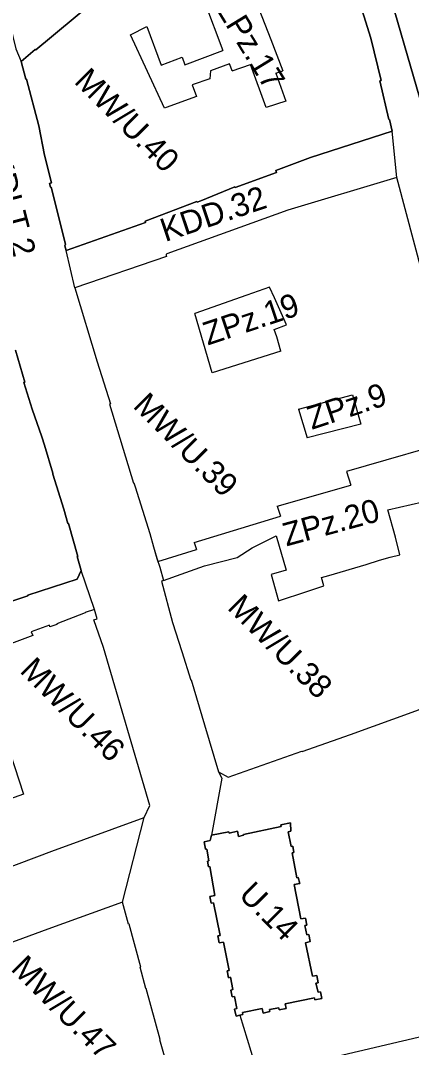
# Model space of a CAD drawing. Extents: x 7423835 to 7425280, y 5546086 to 5547600.
# Drawn here: x 7424273.1 to 7424373.9, y 5546340.4 to 5546605 of the extents above; entities that cross this region are included whole.
import ezdxf

# ---------------------------------------------------------------- set-up
doc = ezdxf.new("R2010")
doc.units = 0
for name, color, linetype in [('linie rozgraniczające', 7, 'Continuous'), ('obowiazujace linie zabudowy', 7, 'Continuous'), ('przeznaczenia terenów', 7, 'Continuous')]:
    doc.layers.add(name, color=color, linetype=linetype)

msp = doc.modelspace()

# ---------------------------------------------------------------- linework, layer by layer
at = {"layer": 'linie rozgraniczające'}
for p, q in [((7424320.53, 5546609.85), (7424325.27, 5546597.26)), ((7424327.69, 5546592.07), (7424332.39, 5546593.73)), ((7424370.16, 5546564.59), (7424368.92, 5546576.52)), ((7424287.1, 5546536.15), (7424284.89, 5546545.76)), ((7424340.24, 5546519.82), (7424322.49, 5546514.25)), ((7424344.77, 5546504.87), (7424346.97, 5546497.47)), ((7424339.31, 5546479.88), (7424358.24, 5546485.3)), ((7424339.31, 5546479.88), (7424340.11, 5546477.35)), ((7424292.16, 5546453.27), (7424288.73, 5546463.32)), ((7424299.42, 5546377.82), (7424304.94, 5546399.71)), ((7424300.93, 5546372.18), (7424299.42, 5546377.82))]:
    msp.add_line(p, q, dxfattribs=at)
for points in [[(7424415.44, 5546675.99), (7424420.93, 5546660.04), (7424421.75, 5546657.53), (7424423.79, 5546651.25), (7424427.88, 5546638.9), (7424441.46, 5546599.12), (7424429.54, 5546594.89), (7424419.97, 5546592.1), (7424408.6, 5546588.75), (7424395.96, 5546584.68), (7424377.65, 5546579.36), (7424357.5, 5546649.05), (7424367.44, 5546652.38), (7424372.88, 5546654.73), (7424377.74, 5546656.83), (7424384.62, 5546660.5)], [(7424264.54, 5546627.07), (7424265.35, 5546624.27), (7424271.84, 5546597.69), (7424273.24, 5546594.48)], [(7424357.59, 5546619.22), (7424363.45, 5546600.46), (7424366.11, 5546589.55), (7424365.71, 5546589.45), (7424368.07, 5546579.5), (7424368.22, 5546579.54), (7424368.92, 5546576.52), (7424347.88, 5546569.7), (7424338.93, 5546566.38), (7424339.13, 5546565.91), (7424328.45, 5546561.99), (7424328.37, 5546562.15), (7424323.98, 5546560.37), (7424319.59, 5546558.59), (7424318.62, 5546558.21), (7424318.55, 5546558.42), (7424305.2, 5546553.33), (7424305.32, 5546552.95), (7424284.89, 5546545.76)], [(7424273.24, 5546594.48), (7424276.9, 5546597.55), (7424277.06, 5546597.51), (7424281.07, 5546600.81), (7424295.83, 5546613.18)], [(7424332.31, 5546613.36), (7424332.85, 5546612.12), (7424333.77, 5546610), (7424337.62, 5546600.12), (7424340.73, 5546592.1)], [(7424327.02, 5546593.9), (7424322.04, 5546592.04), (7424321.89, 5546590.04), (7424317.36, 5546588.44), (7424318.47, 5546585.43), (7424310.68, 5546582.61), (7424310.22, 5546582.44), (7424301.42, 5546601.32), (7424305.67, 5546603.51), (7424309.39, 5546593.55), (7424314.73, 5546595.56), (7424315.44, 5546593.63), (7424325.27, 5546597.26)], [(7424284.89, 5546545.76), (7424284.49, 5546547), (7424284.72, 5546547.36), (7424281.02, 5546562.11), (7424280.81, 5546562.07), (7424280.53, 5546563.02), (7424281.05, 5546563.17), (7424279.29, 5546570.3), (7424277.83, 5546577.87), (7424274.66, 5546589.92), (7424274.49, 5546589.88), (7424273.24, 5546594.48)], [(7424327.69, 5546592.07), (7424327.35, 5546593), (7424327.02, 5546593.9)], [(7424338.89, 5546591.48), (7424341.49, 5546584.22), (7424336.39, 5546582.59), (7424332.39, 5546593.73)], [(7424338.89, 5546591.48), (7424340.73, 5546592.1)], [(7424385.33, 5546507.45), (7424379.08, 5546531), (7424370.16, 5546564.59), (7424342, 5546556.12), (7424329.64, 5546551.71), (7424310.79, 5546544.94), (7424310.68, 5546544.73), (7424310.61, 5546544.48), (7424310.69, 5546544.25), (7424287.1, 5546536.15)], [(7424287.1, 5546536.15), (7424292.88, 5546517.09), (7424296.33, 5546506.24), (7424296.04, 5546506.15), (7424302.24, 5546485.85), (7424302.32, 5546485.88), (7424302.63, 5546484.87), (7424306.47, 5546472.83), (7424307.4, 5546469.44), (7424308.26, 5546466.39), (7424309.04, 5546464.17), (7424309.97, 5546460.74), (7424309.47, 5546460.57), (7424312.24, 5546449.9), (7424314.71, 5546442.42), (7424316.97, 5546435.09), (7424317.08, 5546435.11), (7424320.55, 5546423.54), (7424324.12, 5546411.44), (7424326.63, 5546410.04)], [(7424337.29, 5546536.31), (7424331.48, 5546534.27), (7424318.01, 5546529.55)], [(7424340.24, 5546519.82), (7424339.19, 5546523.54), (7424338.53, 5546525.42), (7424341.71, 5546526.6), (7424338.55, 5546533.55), (7424337.29, 5546536.31)], [(7424322.49, 5546514.25), (7424318.01, 5546529.55)], [(7424271.82, 5546520.1), (7424274.2, 5546511.86), (7424273.9, 5546511.79), (7424276.09, 5546504.9), (7424278.55, 5546497.74), (7424279.24, 5546495.57), (7424281.46, 5546488.37), (7424281.43, 5546488.18), (7424284.22, 5546479.08), (7424285.31, 5546475.44), (7424285.44, 5546475.42), (7424287.86, 5546466.93), (7424287.67, 5546466.89), (7424288.73, 5546463.32), (7424287.7, 5546461.12), (7424274.94, 5546456.95), (7424275, 5546456.78), (7424265.73, 5546453.71)], [(7424344.77, 5546504.87), (7424358.68, 5546508.58), (7424360.81, 5546501.03), (7424346.97, 5546497.47)], [(7424388.19, 5546497.72), (7424357.13, 5546488.82), (7424358.24, 5546485.3)], [(7424309.97, 5546460.74), (7424314.5, 5546462.36), (7424320.52, 5546464.53), (7424328.99, 5546466.65), (7424332.85, 5546469.12), (7424335.89, 5546470.68), (7424339.01, 5546472.28), (7424339.01, 5546472.28), (7424341.59, 5546463.44), (7424337.68, 5546462.29), (7424339.65, 5546455.53), (7424346.89, 5546457.93), (7424351.28, 5546459.38), (7424350.66, 5546461.47), (7424352.59, 5546461.99), (7424362.22, 5546464.88), (7424365.62, 5546465.95), (7424368.4, 5546466.76), (7424370.9, 5546467.32), (7424369.82, 5546471.89), (7424367.79, 5546478.91), (7424376.8, 5546481.03), (7424376.65, 5546481.65), (7424391.22, 5546485.25)], [(7424317.89, 5546470.5), (7424340.11, 5546477.35)], [(7424326.63, 5546410.04), (7424345.67, 5546416.79), (7424345.72, 5546416.64), (7424358.22, 5546421.09), (7424374.99, 5546427.15), (7424393.4, 5546434.44), (7424393.66, 5546433.71), (7424402.17, 5546436.72), (7424403.6, 5546439.53), (7424394.5, 5546472.74)], [(7424308.52, 5546465.65), (7424318.45, 5546468.71)], [(7424317.89, 5546470.5), (7424318.45, 5546468.71)], [(7424240.49, 5546375.59), (7424248.17, 5546378.38), (7424248.08, 5546378.7), (7424268.21, 5546386.13), (7424281.2, 5546390.99), (7424304.94, 5546399.71), (7424306.43, 5546402.78), (7424294.5, 5546443.44), (7424292.01, 5546450.59), (7424292.84, 5546450.88), (7424292.16, 5546453.27), (7424289.77, 5546452.48), (7424289.8, 5546452.37), (7424282.41, 5546449.55), (7424282.47, 5546449.36), (7424280.68, 5546448.76), (7424280.52, 5546449.23), (7424275.85, 5546447.51), (7424276.23, 5546446.57), (7424264.92, 5546442.34), (7424241.57, 5546433.72), (7424225.71, 5546428.05)], [(7424329.68, 5546348.73), (7424333.41, 5546336.36), (7424335.31, 5546335.37), (7424338.04, 5546334.78), (7424340.75, 5546335.13), (7424350.4, 5546337.18), (7424412.55, 5546351.75), (7424415.01, 5546352.54), (7424417.37, 5546354.37), (7424418.62, 5546356.9), (7424418.49, 5546360.03), (7424406.49, 5546406.68), (7424405.05, 5546415.06), (7424405.06, 5546424.89), (7424402.17, 5546436.72)], [(7424269.29, 5546419.67), (7424273.84, 5546405.65), (7424262.72, 5546401.71), (7424260.84, 5546401.05), (7424253.87, 5546398.58), (7424246.23, 5546424.99), (7424252.16, 5546427.18), (7424253.74, 5546427.76), (7424258.94, 5546429.68), (7424260.77, 5546424.62), (7424262.06, 5546425.08), (7424267.36, 5546426.7), (7424267.99, 5546424.81)], [(7424324.12, 5546411.44), (7424325.03, 5546409.84), (7424322.34, 5546395.11)], [(7424299.42, 5546377.82), (7424280.16, 5546370.93), (7424245.49, 5546358.22), (7424249.04, 5546346.02), (7424251.62, 5546336.13)], [(7424311.68, 5546333), (7424309.04, 5546342.36), (7424309.11, 5546342.46), (7424305.5, 5546355.6), (7424305.42, 5546355.59), (7424303.94, 5546361.08), (7424304.09, 5546361.12), (7424301.09, 5546372.23), (7424300.93, 5546372.18)]]:
    msp.add_lwpolyline(points, dxfattribs=at)
msp.add_lwpolyline([(7424322.34, 5546395.11), (7424326.82, 5546396.02), (7424326.91, 5546395.63), (7424329.06, 5546396.19), (7424329.26, 5546394.81), (7424330.61, 5546395.1), (7424330.57, 5546395.31), (7424340.28, 5546397.34), (7424340.23, 5546397.77), (7424342.67, 5546398.28), (7424342.8, 5546396.14), (7424342.12, 5546396.02), (7424342.88, 5546392.18), (7424343.27, 5546392.26), (7424343.61, 5546390.69), (7424343.18, 5546390.6), (7424344.34, 5546384.1), (7424344.72, 5546384.2), (7424345.11, 5546382.65), (7424343.65, 5546382.37), (7424345.4, 5546373.52), (7424346.55, 5546373.74), (7424346.92, 5546371.95), (7424346.4, 5546371.84), (7424346.91, 5546369.44), (7424347.41, 5546369.52), (7424347.77, 5546367.75), (7424346.61, 5546367.39), (7424348.36, 5546358.76), (7424349.52, 5546358.97), (7424349.82, 5546357.11), (7424349.25, 5546357.02), (7424349.85, 5546354.67), (7424350.41, 5546354.76), (7424350.75, 5546353.02), (7424348.97, 5546352.67), (7424348.86, 5546353.22), (7424341.36, 5546351.63), (7424341.58, 5546350.47), (7424339.81, 5546350.12), (7424339.7, 5546350.66), (7424337.27, 5546350.19), (7424337.37, 5546349.65), (7424335.62, 5546349.28), (7424335.39, 5546350.45), (7424330.32, 5546349.44), (7424330.44, 5546348.9), (7424329.68, 5546348.73), (7424328.66, 5546348.51), (7424328.27, 5546350.28), (7424328.87, 5546350.43), (7424328.23, 5546353.57), (7424327.68, 5546353.46), (7424327.33, 5546355.21), (7424327.87, 5546355.33), (7424327.23, 5546358.49), (7424326.7, 5546358.39), (7424326.37, 5546360.13), (7424326.92, 5546360.25), (7424325.43, 5546367.59), (7424324.34, 5546367.39), (7424324, 5546369.15), (7424324.55, 5546369.26), (7424322.82, 5546377.65), (7424322.25, 5546377.57), (7424321.91, 5546379.32), (7424323.16, 5546379.56), (7424321.91, 5546387.04), (7424321.58, 5546386.98), (7424321.32, 5546388.42), (7424321.63, 5546388.48), (7424321.15, 5546391.53), (7424320.8, 5546391.48), (7424320.41, 5546393.42), (7424321.96, 5546393.76)], close=True, dxfattribs=at)
at = {"layer": 'obowiazujace linie zabudowy'}
msp.add_line((7424300.93, 5546372.18), (7424299.42, 5546377.82), dxfattribs=at)
for points in [[(7424367.44, 5546652.38), (7424357.5, 5546649.05), (7424377.65, 5546579.36), (7424395.96, 5546584.68), (7424408.6, 5546588.75), (7424419.97, 5546592.1), (7424429.54, 5546594.89), (7424441.46, 5546599.12), (7424427.88, 5546638.9), (7424421.71, 5546657.52)], [(7424284.89, 5546545.76), (7424305.32, 5546552.95), (7424305.2, 5546553.33), (7424318.55, 5546558.42), (7424318.62, 5546558.21), (7424319.59, 5546558.59), (7424323.98, 5546560.37), (7424328.37, 5546562.15), (7424328.45, 5546561.99), (7424339.13, 5546565.91), (7424338.93, 5546566.38), (7424347.88, 5546569.7), (7424368.92, 5546576.52), (7424368.22, 5546579.54), (7424368.07, 5546579.5), (7424365.71, 5546589.45), (7424366.11, 5546589.55), (7424363.45, 5546600.46), (7424357.59, 5546619.22)], [(7424295.83, 5546613.18), (7424281.07, 5546600.81), (7424277.06, 5546597.51), (7424276.9, 5546597.55), (7424273.24, 5546594.48)], [(7424273.24, 5546594.48), (7424274.49, 5546589.88), (7424274.66, 5546589.92), (7424277.83, 5546577.87), (7424279.29, 5546570.3), (7424281.05, 5546563.17), (7424280.53, 5546563.02), (7424280.81, 5546562.07), (7424281.02, 5546562.11), (7424284.72, 5546547.36), (7424284.49, 5546547), (7424284.89, 5546545.76)], [(7424385.33, 5546507.45), (7424379.08, 5546531), (7424370.16, 5546564.59), (7424342, 5546556.12), (7424329.64, 5546551.71), (7424310.79, 5546544.94), (7424310.68, 5546544.73), (7424310.61, 5546544.48), (7424310.69, 5546544.25), (7424287.1, 5546536.15)], [(7424287.1, 5546536.15), (7424292.88, 5546517.09), (7424296.33, 5546506.24), (7424296.04, 5546506.15), (7424302.24, 5546485.85), (7424302.32, 5546485.88), (7424302.63, 5546484.87), (7424306.47, 5546472.83), (7424307.4, 5546469.44), (7424308.47, 5546465.64)], [(7424265.73, 5546453.71), (7424275, 5546456.78), (7424274.94, 5546456.95), (7424287.7, 5546461.12), (7424288.73, 5546463.32), (7424287.67, 5546466.89), (7424287.86, 5546466.93), (7424285.44, 5546475.42), (7424285.31, 5546475.44), (7424284.22, 5546479.08), (7424281.43, 5546488.18), (7424281.46, 5546488.37), (7424279.24, 5546495.57), (7424278.55, 5546497.74), (7424276.09, 5546504.9), (7424273.9, 5546511.79), (7424274.2, 5546511.86), (7424271.82, 5546520.1)], [(7424326.63, 5546410.04), (7424345.67, 5546416.79), (7424345.72, 5546416.64), (7424358.22, 5546421.09), (7424374.99, 5546427.15), (7424393.4, 5546434.44), (7424393.66, 5546433.71), (7424402.17, 5546436.72), (7424403.6, 5546439.53), (7424394.5, 5546472.74)], [(7424309.97, 5546460.74), (7424309.47, 5546460.57), (7424312.24, 5546449.9), (7424314.71, 5546442.42), (7424316.97, 5546435.09), (7424317.08, 5546435.11), (7424320.55, 5546423.54), (7424324.12, 5546411.44), (7424326.63, 5546410.04)], [(7424240.49, 5546375.59), (7424248.17, 5546378.38), (7424248.08, 5546378.7), (7424268.21, 5546386.13), (7424281.2, 5546390.99), (7424304.94, 5546399.71), (7424306.43, 5546402.78), (7424294.5, 5546443.44), (7424292.01, 5546450.59), (7424292.84, 5546450.88), (7424292.16, 5546453.27), (7424289.77, 5546452.48), (7424289.8, 5546452.37), (7424282.41, 5546449.55), (7424282.47, 5546449.36), (7424280.68, 5546448.76), (7424280.52, 5546449.23), (7424275.85, 5546447.51), (7424276.23, 5546446.57), (7424264.92, 5546442.34), (7424241.57, 5546433.72), (7424225.71, 5546428.05)], [(7424299.42, 5546377.82), (7424280.16, 5546370.93), (7424245.49, 5546358.22), (7424249.04, 5546346.02), (7424251.62, 5546336.13)], [(7424311.68, 5546333), (7424309.04, 5546342.36), (7424309.11, 5546342.46), (7424305.5, 5546355.6), (7424305.42, 5546355.59), (7424303.94, 5546361.08), (7424304.09, 5546361.12), (7424301.09, 5546372.23), (7424300.93, 5546372.18)]]:
    msp.add_lwpolyline(points, dxfattribs=at)
msp.add_lwpolyline([(7424322.34, 5546395.11), (7424321.96, 5546393.76), (7424320.41, 5546393.42), (7424320.8, 5546391.48), (7424321.15, 5546391.53), (7424321.63, 5546388.48), (7424321.32, 5546388.42), (7424321.58, 5546386.98), (7424321.91, 5546387.04), (7424323.16, 5546379.56), (7424321.91, 5546379.32), (7424322.25, 5546377.57), (7424322.82, 5546377.65), (7424324.55, 5546369.26), (7424324, 5546369.15), (7424324.34, 5546367.39), (7424325.43, 5546367.59), (7424326.92, 5546360.25), (7424326.37, 5546360.13), (7424326.7, 5546358.39), (7424327.23, 5546358.49), (7424327.87, 5546355.33), (7424327.33, 5546355.21), (7424327.68, 5546353.46), (7424328.23, 5546353.57), (7424328.87, 5546350.43), (7424328.27, 5546350.28), (7424328.66, 5546348.51), (7424329.68, 5546348.73), (7424330.44, 5546348.9), (7424330.32, 5546349.44), (7424335.39, 5546350.45), (7424335.62, 5546349.28), (7424337.37, 5546349.65), (7424337.27, 5546350.19), (7424339.7, 5546350.66), (7424339.81, 5546350.12), (7424341.58, 5546350.47), (7424341.36, 5546351.63), (7424348.86, 5546353.22), (7424348.97, 5546352.67), (7424350.75, 5546353.02), (7424350.41, 5546354.76), (7424349.85, 5546354.67), (7424349.25, 5546357.02), (7424349.82, 5546357.11), (7424349.52, 5546358.97), (7424348.36, 5546358.76), (7424346.61, 5546367.39), (7424347.77, 5546367.75), (7424347.41, 5546369.52), (7424346.91, 5546369.44), (7424346.4, 5546371.84), (7424346.92, 5546371.95), (7424346.55, 5546373.74), (7424345.4, 5546373.52), (7424343.65, 5546382.37), (7424345.11, 5546382.65), (7424344.72, 5546384.2), (7424344.34, 5546384.1), (7424343.18, 5546390.6), (7424343.61, 5546390.69), (7424343.27, 5546392.26), (7424342.88, 5546392.18), (7424342.12, 5546396.02), (7424342.8, 5546396.14), (7424342.67, 5546398.28), (7424340.23, 5546397.77), (7424340.28, 5546397.34), (7424330.57, 5546395.31), (7424330.61, 5546395.1), (7424329.26, 5546394.81), (7424329.06, 5546396.19), (7424326.91, 5546395.63), (7424326.82, 5546396.02)], close=True, dxfattribs=at)

# ---------------------------------------------------------------- texts
at = {"layer": 'przeznaczenia terenów'}
for s, rotation, p in [('ZPz.17', 301.4234, (7424323.24, 5546608.23)), ('MW/U.40', 314.9764, (7424286.68, 5546589.1)), ('KDLT.2', 284.4891, (7424264.58, 5546570.09)), ('KDD.32', 18.5988, (7424310.4, 5546547.94)), ('ZPz.19', 18.4233, (7424321.36, 5546521.26)), ('ZPz.9', 18.4233, (7424348.19, 5546499.53)), ('MW/U.39', 314.9764, (7424301.83, 5546505.47)), ('ZPz.20', 15.2282, (7424341.64, 5546469.5)), ('MW/U.38', 314.9764, (7424326.16, 5546453.51)), ('MW/U.46', 314.9764, (7424272.69, 5546437.24)), ('U.14', 314.9764, (7424329.07, 5546379.43)), ('MW/U.47', 314.9764, (7424270.36, 5546360.44))]:
    msp.add_text(s, height=6, rotation=rotation, dxfattribs=at).set_placement(p)

doc.saveas('drawing.dxf')
